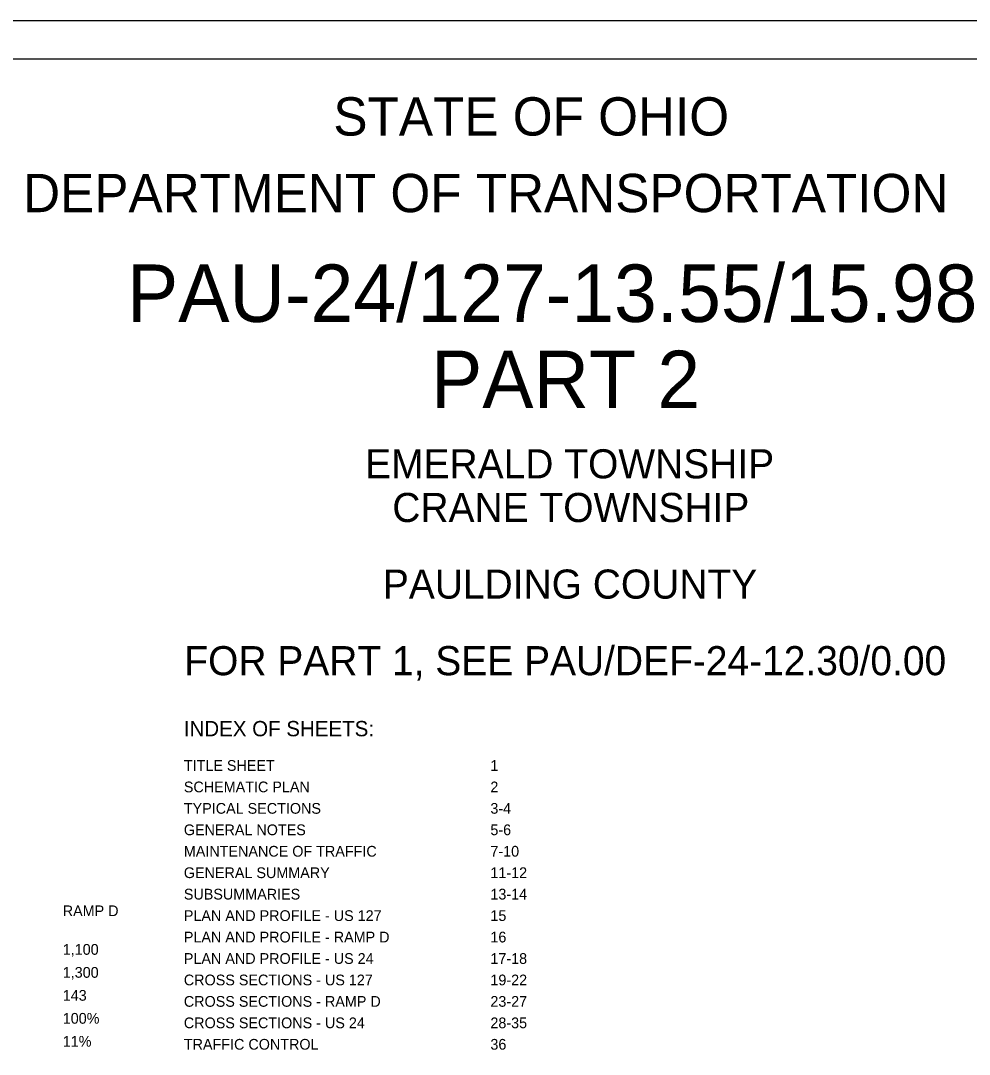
# Model space of a CAD drawing. Extents: x 0 to 64.8, y -5 to 22.
# Drawn here: x 9.72 to 22.09, y 8.51 to 22 of the extents above; entities that cross this region are included whole.
import ezdxf

# ---------------------------------------------------------------- set-up
doc = ezdxf.new("R2010")
doc.units = 0
for name, color, linetype in [('SH_Border', 7, 'Continuous'), ('SH_Cut_Line', 7, 'Continuous'), ('SH_Text', 7, 'Continuous')]:
    doc.layers.add(name, color=color, linetype=linetype)

msp = doc.modelspace()

# ---------------------------------------------------------------- linework, layer by layer
at = {"layer": 'SH_Border'}
msp.add_lwpolyline([(1.5, 21.5), (33.5, 21.5), (33.5, 0.5), (1.5, 0.5)], close=True, dxfattribs=at)
at = {"layer": 'SH_Cut_Line'}
msp.add_lwpolyline([(0, 0), (34, 0), (34, 22), (0, 22)], close=True, dxfattribs=at)

# ---------------------------------------------------------------- texts
at = {"layer": 'SH_Text'}
for s, height, p in [('STATE OF OHIO', 0.5, (13.795, 20.5)), ('DEPARTMENT OF TRANSPORTATION', 0.5, (9.747, 19.5)), ('PAU-24/127-13.55/15.98', 0.75, (11.102, 18.067)), ('PART 2', 0.75, (15.069, 16.942)), ('EMERALD TOWNSHIP', 0.38, (14.21, 16.025)), ('CRANE TOWNSHIP', 0.38, (14.564, 15.455)), ('PAULDING COUNTY', 0.38, (14.441, 14.455)), ('FOR PART 1, SEE PAU/DEF-24-12.30/0.00', 0.38, (11.85, 13.455)), ('INDEX OF SHEETS:', 0.2, (11.844, 12.658)), ('TITLE SHEET', 0.14, (11.844, 12.207)), ('1', 0.14, (15.844, 12.207)), ('SCHEMATIC PLAN', 0.14, (11.844, 11.927)), ('2', 0.14, (15.844, 11.927)), ('TYPICAL SECTIONS', 0.14, (11.844, 11.647)), ('3-4', 0.14, (15.844, 11.647)), ('GENERAL NOTES', 0.14, (11.844, 11.367)), ('5-6', 0.14, (15.844, 11.367)), ('MAINTENANCE OF TRAFFIC', 0.14, (11.844, 11.087)), ('7-10', 0.14, (15.844, 11.087)), ('GENERAL SUMMARY', 0.14, (11.844, 10.807)), ('11-12', 0.14, (15.844, 10.807)), ('SUBSUMMARIES', 0.14, (11.844, 10.527)), ('13-14', 0.14, (15.844, 10.527)), ('RAMP D', 0.14, (10.264, 10.31)), ('PLAN AND PROFILE - US 127', 0.14, (11.844, 10.247)), ('15', 0.14, (15.844, 10.247)), ('PLAN AND PROFILE - RAMP D', 0.14, (11.844, 9.967)), ('16', 0.14, (15.844, 9.967)), ('1,100', 0.14, (10.264, 9.806)), ('PLAN AND PROFILE - US 24 ', 0.14, (11.844, 9.687)), ('17-18', 0.14, (15.844, 9.687)), ('1,300', 0.14, (10.264, 9.506)), ('CROSS SECTIONS - US 127', 0.14, (11.844, 9.407)), ('19-22', 0.14, (15.844, 9.407)), ('143', 0.14, (10.264, 9.206)), ('CROSS SECTIONS - RAMP D ', 0.14, (11.844, 9.127)), ('23-27', 0.14, (15.844, 9.127)), ('100%', 0.14, (10.264, 8.906)), ('CROSS SECTIONS - US 24', 0.14, (11.844, 8.847)), ('28-35', 0.14, (15.844, 8.847)), ('11%', 0.14, (10.264, 8.606)), ('TRAFFIC CONTROL', 0.14, (11.844, 8.567)), ('36', 0.14, (15.844, 8.567))]:
    msp.add_text(s, height=height, dxfattribs=at).set_placement(p)

doc.saveas('drawing.dxf')
